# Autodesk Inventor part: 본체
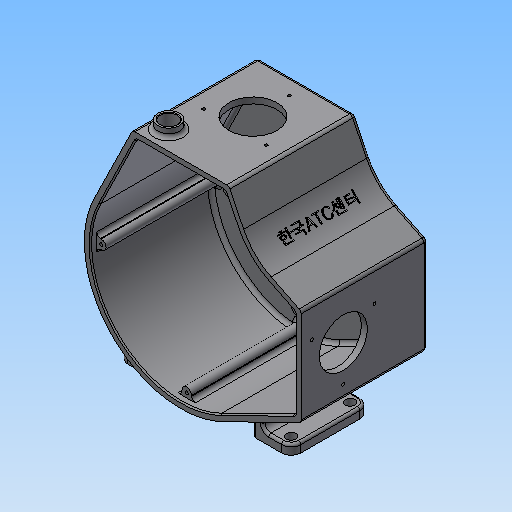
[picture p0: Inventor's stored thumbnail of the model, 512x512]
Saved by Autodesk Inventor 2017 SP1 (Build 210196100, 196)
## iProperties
Created: 2017-05
Part Number: 본체
Material: 일반
Document SubType Name: Modeling
Designer: mduedu
Density: 1 g/cm^3
Appearance: 기본값
Mass: 496.576 g
Surface Area: 1824.08 cm^2
Volume: 496.576 cm^3
Author: mduedu
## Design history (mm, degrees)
sketch "스케치1"
  geometry: L1 (-71.801, 35.28)-(-40, 100); L2 (-40, 100)-(40, 100); L3 (40, 100)-(59.768, 59.768); L4 (59.768, 59.768)-(100, 40); L5 (100, 40)-(100, -40); L6 (100, -40)-(35.28, -71.801); A1 r 80 centre (0, 0) between (-71.801, 35.28) and (35.28, -71.801); 3 further points
  constraints: 12 end point, 4 tangent, 2 midpoint, 2 point on circle, 1 centre point, 1 coincident, 1 horizontal, 1 horizontal alignment, 1 perpendicular, 1 vertical alignment
  dimensions: "d0" = 160 diameter of A1; "d2" = 100 distance from line of L2 point (0, 0); "d3" = 100 distance from line of L5 point (0, 0); "d4" = 80 distance of L1.end L2.end; "d5" = 80 distance of L4.end L5.end
extrude "돌출1" new body sketch "스케치1" distance "d6" = 5; taper "d7" = 0 deg
fillet "모깎기1" dims "d8" = 50
sketch "스케치2"
  geometry: C1 r 22 at (0, 0); 1 further point
  constraints: 1 centre point, 1 coincident
  dimensions: "d9" = 44 diameter of C1
extrude "돌출2" join sketch "스케치2" distance "d10" = 22.5; taper "d11" = 0 deg
sketch "스케치3"
  geometry: C1 r 18.5 at (0, 0); 1 further point
  constraints: 1 centre point, 1 coincident
  dimensions: "d12" = 37 diameter of C1
extrude "돌출3" cut sketch "스케치3" distance "d13" = 9; taper "d14" = 0 deg
fillet "모깎기2" dims "d15" = 3
sketch "스케치4"
  geometry: L1 (35.28, -71.801)-(100, -40) reference; L2 (100, -40)-(100, 40) reference; L3 (100, 40)-(75.073, 52.248) reference; L4 (52.248, 75.073)-(40, 100) reference; L5 (40, 100)-(-40, 100) reference; L6 (-40, 100)-(-71.801, 35.28) reference; L7 (-36.886, 95)-(36.886, 95); L8 (36.886, 95)-(47.76, 72.868); L9 (72.868, 47.76)-(95, 36.886); L10 (95, 36.886)-(95, -36.886); L11 (95, -36.886)-(33.075, -67.313); L12 (-67.313, 33.075)-(-36.886, 95); C1 r 25 at (0, 0) reference; A1 r 50 centre (97.123, 97.123) between (52.248, 75.073) and (75.073, 52.248) reference; A2 r 80 centre (0, 0) between (-71.801, 35.28) and (35.28, -71.801) reference; A3 r 55 centre (97.123, 97.123) between (47.76, 72.868) and (72.868, 47.76); A4 r 75 centre (0, 0) between (-67.313, 33.075) and (33.075, -67.313); 1 further point
  constraints: 12 end point, 4 point on circle, 2 centre point, 7 other
  dimensions: "d16" = 5 distance between parallel lines of L7 L5
extrude "돌출4" join sketch "스케치4" distance "d17" = 100; taper "d18" = 0 deg
sketch "스케치5"
  geometry: L1 (80, 0)-(0, 0) reference; C1 r 20 at (40, -45); 2 further points
  constraints: 1 centre point, 1 midpoint, 1 vertical alignment
  dimensions: "d19" = 40 diameter of C1; "d21" = 45 distance from line of C1.centre L1
extrude "돌출5" cut sketch "스케치5" stored distance "d22" = 100; taper "d23" = 0 deg
sketch "스케치6"
  geometry: L1 (0, 0)-(0, -105) reference; L2 (80, -105)-(0, -105) reference; C1 r 9 at (14, -89); 1 further point
  constraints: 1 centre point
  dimensions: "d24" = 18 diameter of C1; "d26" = 14 distance from line of C1.centre L1; "d27" = 16 distance from line of C1.centre L2
extrude "돌출6" join sketch "스케치6" distance "d28" = 7; taper "d29" = 0 deg
hole "구멍1" diameter "d32" = 14; stored, may be unused: countersink angle "d36" = 90 deg, drill point angle "d38" = 118 deg; dims "d33" = 6, "d34" = 4, "d35" = 2, "d37" = 8, "d39" = 10, "d40" = 10
sketch "스케치7"
  geometry: L1 (-105, 0)-(-105, 80) reference; L2 (0, 0)-(0, 80) reference; C1 r 20 at (-70, 40); 2 further points
  constraints: 1 centre point, 1 horizontal alignment, 1 midpoint
  dimensions: "d41" = 40 diameter of C1; "d42" = 35 distance from line of C1.centre L1
extrude "돌출7" cut sketch "스케치7" stored distance "d43" = 7; taper "d44" = 0 deg
node "작업 평면1"
sketch "스케치8"
  geometry: L1 (47.76, 72.868)-(36.886, 95) reference; L2 (36.886, 95)-(-36.886, 95) reference; L3 (-36.886, 95)-(-67.313, 33.075) reference; L4 (33.075, -67.313)-(95, -36.886) reference; L5 (95, -36.886)-(95, 36.886) reference; L6 (95, 36.886)-(72.868, 47.76) reference; L7 (95, 36.886)-(95, -36.886) reference; L8 (-36.886, 95)-(36.886, 95) reference; L9 (36.886, 95)-(47.76, 72.868) reference; L10 (-71, 4)-(-74.893, 4); L11 (-71, -4)-(-74.893, -4); L12 (-4, -71)-(-4, -74.893); L13 (4, -71)-(4, -74.893); L14 (30.394, 91)-(30.394, 95); L15 (34.394, 87)-(40.817, 87); L16 (30.394, 95)-(36.886, 95); L17 (36.886, 95)-(37.984, 92.764); L18 (91, 30.394)-(95, 30.394); L19 (87, 34.394)-(87, 40.817); L20 (87, 40.817)-(95, 36.886); L21 (95, 36.886)-(95, 30.394); C1 r 25 at (0, 0) reference; A1 r 75 centre (0, 0) between (-67.313, 33.075) and (33.075, -67.313) reference; A2 r 55 centre (97.123, 97.123) between (47.76, 72.868) and (72.868, 47.76) reference; A3 r 4 centre (-71, 0) between (-71, 4) and (-71, -4); A4 r 4 centre (0, -71) between (-4, -71) and (4, -71); A5 r 4 centre (34.394, 91) between (30.394, 91) and (34.394, 87); A6 r 75 centre (0, 0) between (-67.313, 33.075) and (33.075, -67.313) reference; A7 r 4 centre (91, 34.394) between (91, 30.394) and (87, 34.394); 1 further point
  constraints: 24 end point, 17 point on circle, 14 tangent, 5 point on line, 4 centre point, 3 equal radius, 3 perpendicular, 3 vertical, 2 collinear, 2 horizontal, 1 horizontal alignment, 1 parallel, 1 vertical alignment
  dimensions: "d46" = 8 diameter of A3
extrude "돌출8" join sketch "스케치8" stored distance "d49" = 7; taper "d50" = 0 deg
node "작업 평면2"
sketch "스케치9"
  geometry: L1 (71.801, 0)-(71.801, 105) reference; L2 (71.801, 0)-(-35.28, 0) reference; L3 (-35.28, 0)-(-35.28, 105) reference; L4 (71.801, 105)-(-35.28, 105) reference; L5 (40, 0)-(40, 105) reference; L6 (71.801, 52.5)-(-35.28, 52.5); L7 (71.801, 20)-(40, 20); L8 (40, 20)-(40, 85); L9 (40, 85)-(71.801, 85); L10 (71.801, 85)-(71.801, 20); 1 further point
  constraints: 10 end point, 2 midpoint, 2 parallel, 2 point on line, 1 horizontal, 1 perpendicular, 1 other
  dimensions: "d52" = 20 distance between parallel lines of L7 L2
extrude "돌출9" join sketch "스케치9" distance "d53" = 8; taper "d54" = 0 deg
fillet "모깎기3" dims "d55" = 8
sketch "스케치10"
  geometry: C1 r 4 at (-63.801, -28); C2 r 4 at (-63.801, -77); A1 r 8 centre (-63.801, -28) between (-63.801, -20) and (-71.801, -28) reference; A2 r 8 centre (-63.801, -77) between (-71.801, -77) and (-63.801, -85) reference; 1 further point
  constraints: 2 centre point, 2 coincident, 1 equal radius
  dimensions: "d56" = 8 diameter of C1
extrude "돌출10" cut sketch "스케치10" stored distance "d57" = 50.5; taper "d58" = 0 deg
sketch "스케치11"
  geometry: L1 (-63.801, -20)-(-40, -20) reference; L2 (-40, -20)-(-40, -85) reference; L3 (-40, -85)-(-63.801, -85) reference; L4 (-71.801, -77)-(-71.801, -28) reference; L5 (71.801, -77)-(71.801, -28) reference; L6 (40, -85)-(63.801, -85) reference; L7 (40, -20)-(40, -85) reference; L8 (63.801, -20)-(40, -20) reference; L9 (-40, -85)-(-48, -85); L10 (-48, -85)-(-48, -20); L11 (-48, -20)-(-40, -20); L12 (-40, -20)-(-40, -85); L13 (40, -85)-(48, -85); L14 (48, -85)-(48, -20); L15 (48, -20)-(40, -20); L16 (40, -20)-(40, -85); C1 r 4 at (-63.801, -28) reference; C2 r 4 at (-63.801, -77) reference; C3 r 4 at (63.801, -28) reference; C4 r 4 at (63.801, -77) reference; A1 r 8 centre (-63.801, -28) between (-63.801, -20) and (-71.801, -28) reference; A2 r 8 centre (-63.801, -77) between (-71.801, -77) and (-63.801, -85) reference; A3 r 8 centre (63.801, -28) between (71.801, -28) and (63.801, -20) reference; A4 r 8 centre (63.801, -77) between (63.801, -85) and (71.801, -77) reference; 1 further point
  constraints: 16 end point, 4 parallel, 2 horizontal, 2 perpendicular, 2 point on line
  dimensions: "d59" = 8 distance of L10.end L11.end; "d61" = 8 distance of L14.end L15.end
extrude "돌출11" join sketch "스케치11" stored distance "d62" = 5; taper "d63" = 0 deg
fillet "모깎기4" dims "d64" = 5
fillet "모깎기5" dims "d65" = 2
fillet "모깎기6" dims "d66" = 2
fillet "모깎기8" dims "d68" = 2
fillet "모깎기9" dims "d70" = 3, "d101" = 1
fillet "모깎기10" dims "d71" = 3
fillet "모깎기11" dims "d72" = 3
fillet "모깎기12" dims "d73" = 3
fillet "모깎기13" dims "d76" = 3
chamfer "모따기1" distance "d77" = 0.5; stored, may be unused: second distance "d78" = 2, angle "d79" = 45 deg
chamfer "모따기2" distance "d87" = 1; stored, may be unused: second distance "d88" = 2, angle "d89" = 45 deg
chamfer "모따기3" distance "d90" = 1; stored, may be unused: second distance "d91" = 2, angle "d92" = 45 deg
sketch "스케치14"
  geometry: 3 further points
  constraints: 3 other
hole "구멍2" sketch "스케치14" at (-55.375, -40), (-3.414, -40), (-29.394, -85) diameter "d93" = 2.459; stored, may be unused: countersink angle "d97" = 90 deg, drill point angle "d99" = 0 deg; dims "d94" = 6, "d95" = 4, "d96" = 2, "d98" = 8
sketch "스케치15"
  geometry: 3 further points
  constraints: 3 other
hole "구멍4" sketch "스케치15" at (-55.981, -14.394), (-4.019, -14.394), (-30, -59.394) diameter "d102" = 2.459; stored, may be unused: countersink angle "d106" = 90 deg, drill point angle "d108" = 0 deg; dims "d103" = 6, "d104" = 4, "d105" = 2, "d107" = 8
sketch "스케치16"
  geometry: 4 further points
  constraints: 4 other
hole "구멍6" sketch "스케치16" at (0, -71), (91, 34.394), (34.394, 91), (-71, 0) diameter "d109" = 2.459; stored, may be unused: countersink angle "d113" = 90 deg, drill point angle "d115" = 120 deg; dims "d110" = 8.5, "d111" = 4, "d112" = 2, "d114" = 10
node "작업 평면4"
sketch "스케치17"
  geometry: 2 further points
  constraints: 1 horizontal alignment, 1 other
  dimensions: "d116" = 52.5 distance of point (0, 16.14) point (52.5, 16.14)
feature "엠보싱2" sketch "스케치17" dims "d117" = 0.5, "d118" = 0
node "솔리드1"
mirror "대칭1"
node "투영된 루프1"
node "투영된 루프2"
node "투영된 루프3"
node "투영된 루프4"
node "투영된 루프5"
other parameters: "d45" = 95
